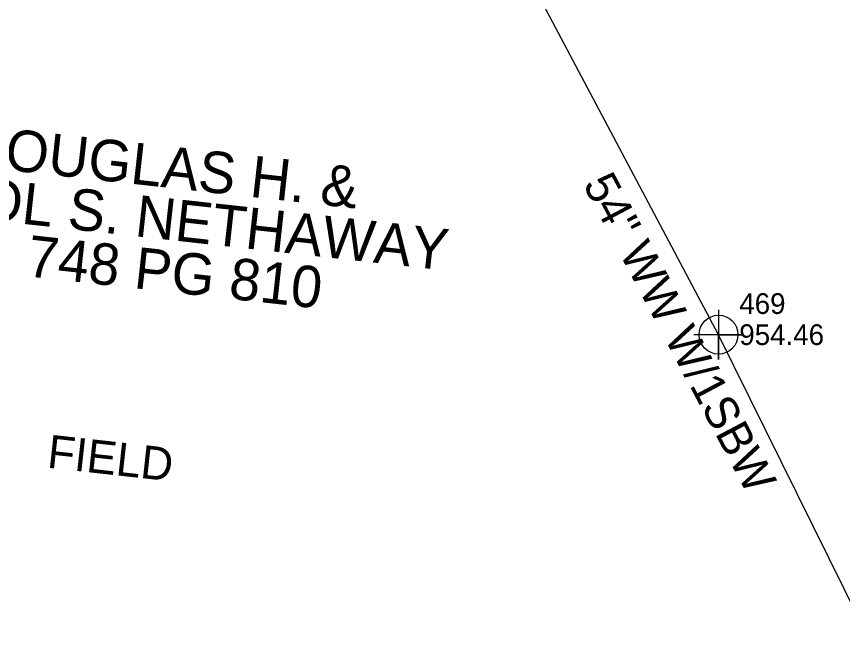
# Model space of a CAD drawing. Extents: x 1150279 to 1151282, y 655434 to 657999.
# Drawn here: x 1150667.5 to 1150767.1, y 656993.5 to 657070.4 of the extents above; entities that cross this region are included whole.
import ezdxf

# ---------------------------------------------------------------- set-up
doc = ezdxf.new("R2010")
doc.units = 0
for name, color, linetype in [('Exist Other Culture Fence Line', 7, 'Continuous'), ('Exist Other Culture Fence Line Cogo Elevation', 7, 'Continuous'), ('Exist Other Culture Fence Line Cogo Number', 7, 'Continuous'), ('Exist Other Culture Fence Line Cogo Point CELL', 7, 'Continuous'), ('Exist Other Culture Fence Line Text', 7, 'Continuous'), ('Exist Property Deed Book Text', 7, 'Continuous'), ('Exist Property Owner Text', 7, 'Continuous'), ('Exist Vegetation Woods Line Text', 7, 'Continuous')]:
    doc.layers.add(name, color=color, linetype=linetype)

msp = doc.modelspace()

# ---------------------------------------------------------------- linework, layer by layer
at = {"layer": 'Exist Other Culture Fence Line'}
msp.add_lwpolyline([(1150771.144, 656993.524), (1150752.14, 657032.017), (1150729.275, 657075.13), (1150719.487, 657093.066), (1150693.827, 657099.275)], dxfattribs=at)
at = {"layer": 'Exist Other Culture Fence Line Cogo Point CELL'}
msp.add_lwpolyline([(1150752.14, 657035.017), (1150752.14, 657029.017), (1150752.14, 657032.017), (1150755.14, 657032.017), (1150749.14, 657032.017)], dxfattribs=at)
msp.add_circle((1150752.14, 657032.017), 2.344, dxfattribs=at)

# ---------------------------------------------------------------- texts
at = {"layer": 'Exist Other Culture Fence Line Cogo Elevation'}
msp.add_text('954.46', height=2.5, dxfattribs=at).set_placement((1150754.64, 657030.767))
at = {"layer": 'Exist Other Culture Fence Line Cogo Number'}
msp.add_text('469', height=2.5, dxfattribs=at).set_placement((1150754.64, 657034.517))
at = {"layer": 'Exist Other Culture Fence Line Text'}
msp.add_text('54" WW W/1SBW', height=4, rotation=297.93951, dxfattribs=at).set_placement((1150735.721, 657050.171))
at = {"layer": 'Exist Property Deed Book Text'}
msp.add_text('DB 748 PG 810', height=5, rotation=353.6867, dxfattribs=at).set_placement((1150657.481, 657040.301))
at = {"layer": 'Exist Property Owner Text'}
for s, p in [('DOUGLAS H. &', (1150661.125, 657052.475)), ('CAROL S. NETHAWAY', (1150648.738, 657047.557))]:
    msp.add_text(s, height=5, rotation=353.6867, dxfattribs=at).set_placement(p)
at = {"layer": 'Exist Vegetation Woods Line Text'}
msp.add_text('FIELD', height=4, rotation=353.6867, dxfattribs=at).set_placement((1150671.044, 657015.972))

doc.saveas('drawing.dxf')
